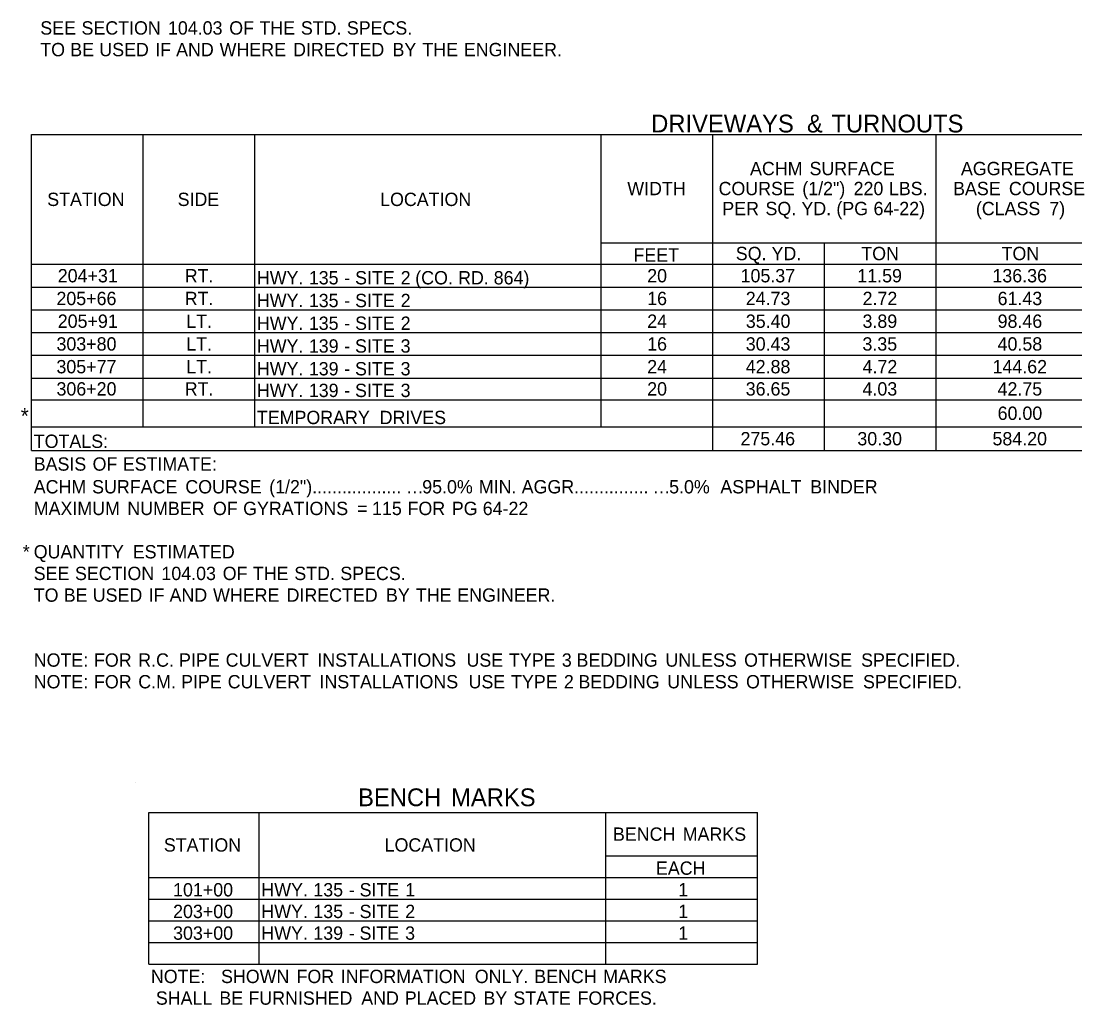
# Model space of a CAD drawing. Extents: x 1955554 to 1962042, y 565952 to 568347.
# Drawn here: x 1956892.3 to 1957366.6, y 566090.6 to 566533.4 of the extents above; entities that cross this region are included whole.
import ezdxf

# ---------------------------------------------------------------- set-up
doc = ezdxf.new("R2010")
doc.units = 0
doc.layers.add('Default', color=7, linetype='Continuous')
doc.layers.add('R_Border', color=7, linetype='Continuous')

msp = doc.modelspace()

# ---------------------------------------------------------------- linework, layer by layer
at = {"layer": 'Default'}
for p, q in [((1956897.02, 566482.45), (1957597.55, 566482.45)), ((1956897.02, 566340.1), (1956897.02, 566482.45)), ((1956897.02, 566340.1), (1956897.02, 566482.45)), ((1956947.23, 566350.82), (1956947.23, 566482.45)), ((1956997.44, 566350.82), (1956997.44, 566482.45)), ((1957153.44, 566350.82), (1957153.44, 566482.45)), ((1957203.65, 566340.1), (1957203.65, 566482.45)), ((1957304.08, 566340.1), (1957304.08, 566482.45)), ((1957153.44, 566433.7), (1957448.87, 566433.7)), ((1957203.65, 566423.95), (1957203.65, 566433.7)), ((1957253.87, 566340.1), (1957253.87, 566433.7)), ((1957304.08, 566340.1), (1957304.08, 566433.7)), ((1956897.02, 566423.95), (1957597.55, 566423.95)), ((1956947.23, 566350.82), (1956947.23, 566423.95)), ((1956997.44, 566350.82), (1956997.44, 566423.95)), ((1957153.44, 566350.82), (1957153.44, 566423.95)), ((1956897.02, 566413.71), (1957597.55, 566413.71)), ((1956897.02, 566403.47), (1957597.55, 566403.47)), ((1956897.02, 566393.24), (1957597.55, 566393.24)), ((1956897.02, 566383), (1957597.55, 566383)), ((1956897.02, 566372.76), (1957597.55, 566372.76)), ((1956897.02, 566363.01), (1957597.55, 566363.01)), ((1956897.02, 566350.82), (1957597.55, 566350.82)), ((1957203.65, 566350.82), (1957253.87, 566350.82)), ((1957203.65, 566340.1), (1957203.65, 566350.82)), ((1957253.87, 566350.82), (1957380.13, 566350.82)), ((1956897.02, 566340.1), (1957597.55, 566340.1)), ((1956949.74, 566177.21), (1957223.72, 566177.21)), ((1956949.74, 566108.96), (1956949.74, 566177.21)), ((1956949.74, 566108.96), (1956949.74, 566177.21)), ((1956999.47, 566108.96), (1956999.47, 566177.21)), ((1957155.47, 566108.96), (1957155.47, 566177.21)), ((1957223.72, 566108.96), (1957223.72, 566177.21)), ((1957155.47, 566157.71), (1957223.72, 566157.71)), ((1957223.72, 566108.96), (1957223.72, 566157.71)), ((1956949.74, 566147.96), (1957223.72, 566147.96)), ((1957155.47, 566108.96), (1957155.47, 566147.96)), ((1956949.74, 566138.21), (1957223.72, 566138.21)), ((1956949.74, 566128.46), (1957223.72, 566128.46)), ((1956949.74, 566118.71), (1957223.72, 566118.71)), ((1956949.74, 566108.96), (1957223.72, 566108.96))]:
    msp.add_line(p, q, dxfattribs=at)
at = {"layer": 'R_Border'}
msp.add_line((1956943.89, 566190.86), (1956943.89, 566190.86), dxfattribs=at)

# ---------------------------------------------------------------- texts
at = {"layer": 'Default'}
for s, height, p in [('SEE', 6, (1956900.93, 566527.36)), (' SECTION', 6, (1956917.26, 566527.36)), (' 104.03', 6, (1956956.17, 566527.36)), (' OF', 6, (1956983.75, 566527.36)), (' THE', 6, (1956997.34, 566527.36)), (' STD.', 6, (1957015.99, 566527.36)), (' SPECS.', 6, (1957036.68, 566527.36)), ('TO', 6, (1956900.93, 566517.61)), (' BE', 6, (1956912.2, 566517.61)), (' USED', 6, (1956925.27, 566517.61)), (' IF', 6, (1956950.44, 566517.61)), (' AND', 6, (1956959.84, 566517.61)), (' WHERE', 6, (1956979.42, 566517.61)), (' DIRECTED', 6, (1957012.5, 566517.61)), (' BY', 6, (1957057.24, 566517.61)), (' THE', 6, (1957070.69, 566517.61)), (' ENGINEER.', 6, (1957089.34, 566517.61)), ('DRIVEWAYS', 8, (1957175.88, 566483.32)), (' &', 8, (1957243.03, 566483.32)), (' TURNOUTS', 8, (1957254.03, 566483.32)), ('ACHM', 6, (1957220.37, 566464.07)), (' SURFACE', 6, (1957244.92, 566464.07)), ('AGGREGATE', 6, (1957315.29, 566464.07)), ('WIDTH', 6, (1957165.13, 566455.07)), ('COURSE', 6, (1957206.22, 566455.07)), (' (1/2")', 6, (1957241.67, 566455.07)), (' 220', 6, (1957264.77, 566455.07)), (' LBS.', 6, (1957280.66, 566455.07)), ('BASE', 6, (1957311.77, 566455.07)), (' COURSE', 6, (1957334.65, 566455.07)), ('STATION', 6, (1956904.06, 566450.2)), ('SIDE', 6, (1956962.76, 566450.2)), ('LOCATION', 6, (1957053.89, 566450.2)), ('PER', 6, (1957207.89, 566446.07)), (' SQ.', 6, (1957225.09, 566446.07)), (' YD.', 6, (1957241.28, 566446.07)), (' (PG', 6, (1957257.01, 566446.07)), (' 64-22)', 6, (1957273.73, 566446.07)), ('(CLASS', 6, (1957322.03, 566446.07)), (' 7)', 6, (1957352.83, 566446.07)), ('FEET', 6, (1957167.92, 566425.15)), ('SQ.', 6, (1957213.96, 566425.82)), (' YD.', 6, (1957227.83, 566425.82)), ('TON', 6, (1957270.46, 566425.82)), ('TON', 6, (1957333.59, 566425.82)), ('204+31', 6, (1956908.8, 566415.83)), ('RT.', 6, (1956965.95, 566415.83)), ('20', 6, (1957174.09, 566415.83)), ('105.37', 6, (1957216.13, 566415.83)), ('11.59', 6, (1957268.67, 566415.83)), ('136.36', 6, (1957329.48, 566415.83)), ('HWY.', 6, (1956998.42, 566414.91)), (' 135', 6, (1957019.57, 566414.91)), (' -', 6, (1957035.54, 566414.91)), (' SITE', 6, (1957040.4, 566414.91)), (' 2', 6, (1957060.92, 566414.91)), (' (CO.', 6, (1957067.46, 566414.91)), (' RD.', 6, (1957086.75, 566414.91)), (' 864)', 6, (1957102.78, 566414.91)), ('205+66', 6, (1956908.21, 566405.59)), ('RT.', 6, (1956965.95, 566405.59)), ('HWY.', 6, (1956998.42, 566404.67)), (' 135', 6, (1957019.57, 566404.67)), (' -', 6, (1957035.54, 566404.67)), (' SITE', 6, (1957040.4, 566404.67)), (' 2', 6, (1957060.92, 566404.67)), ('16', 6, (1957174.08, 566405.59)), ('24.73', 6, (1957218.46, 566405.59)), ('2.72', 6, (1957271.04, 566405.59)), ('61.43', 6, (1957331.81, 566405.59)), ('205+91', 6, (1956908.8, 566395.36)), ('LT.', 6, (1956966.64, 566395.36)), ('HWY.', 6, (1956998.42, 566394.44)), (' 135', 6, (1957019.57, 566394.44)), (' SITE', 6, (1957040.4, 566394.44)), (' 2', 6, (1957060.92, 566394.44)), ('24', 6, (1957174.09, 566395.36)), ('35.40', 6, (1957218.48, 566395.36)), ('3.89', 6, (1957271, 566395.36)), ('98.46', 6, (1957331.81, 566395.36)), (' -', 6, (1957035.54, 566394.44)), ('303+80', 6, (1956908.23, 566385.12)), ('LT.', 6, (1956966.64, 566385.12)), ('HWY.', 6, (1956998.42, 566384.2)), (' 139', 6, (1957019.57, 566384.2)), (' SITE', 6, (1957040.36, 566384.2)), (' 3', 6, (1957060.88, 566384.2)), ('16', 6, (1957174.08, 566385.12)), ('30.43', 6, (1957218.46, 566385.12)), ('3.35', 6, (1957270.98, 566385.12)), ('40.58', 6, (1957331.8, 566385.12)), (' -', 6, (1957035.51, 566384.2)), ('305+77', 6, (1956908.21, 566374.88)), ('LT.', 6, (1956966.64, 566374.88)), ('HWY.', 6, (1956998.42, 566373.96)), (' 139', 6, (1957019.57, 566373.96)), (' SITE', 6, (1957040.36, 566373.96)), (' 3', 6, (1957060.88, 566373.96)), ('24', 6, (1957174.09, 566374.88)), ('42.88', 6, (1957218.46, 566374.88)), ('4.72', 6, (1957271.04, 566374.88)), ('144.62', 6, (1957329.51, 566374.88)), (' -', 6, (1957035.51, 566373.96)), ('306+20', 6, (1956908.23, 566364.89)), ('RT.', 6, (1956965.95, 566364.89)), ('HWY.', 6, (1956998.42, 566364.21)), (' 139', 6, (1957019.57, 566364.21)), (' SITE', 6, (1957040.36, 566364.21)), (' 3', 6, (1957060.88, 566364.21)), ('20', 6, (1957174.09, 566364.89)), ('36.65', 6, (1957218.44, 566364.89)), ('4.03', 6, (1957271.01, 566364.89)), ('42.75', 6, (1957331.79, 566364.89)), (' -', 6, (1957035.51, 566364.21)), ('60.00', 6, (1957331.82, 566353.92)), ('*', 7, (1956892.14, 566352.22)), ('TEMPORARY', 6, (1956998.42, 566352.02)), (' DRIVES', 6, (1957051.46, 566352.02)), ('TOTALS:', 6, (1956897.99, 566341.3)), ('275.46', 6, (1957216.09, 566342.46)), ('30.30', 6, (1957268.69, 566342.46)), ('584.20', 6, (1957329.49, 566342.46)), ('BASIS', 6, (1956897.99, 566331.06)), (' OF', 6, (1956922.25, 566331.06)), (' ESTIMATE:', 6, (1956935.84, 566331.06)), ('ACHM', 6, (1956897.99, 566320.82)), (' SURFACE', 6, (1956922.04, 566320.82)), (' COURSE', 6, (1956963.99, 566320.82)), (' (1/2")..................', 6, (1957001.74, 566320.82)), ('95.0%', 6, (1957072.84, 566320.82)), (' MIN.', 6, (1957096.08, 566320.82)), (' AGGR...............', 6, (1957115.37, 566320.82)), ('5.0%', 6, (1957183.97, 566320.82)), ('  ASPHALT', 6, (1957202.55, 566320.82)), (' BINDER', 6, (1957245.25, 566320.82)), ('MAXIMUM', 6, (1956897.99, 566311.07)), (' NUMBER', 6, (1956937.88, 566311.07)), (' OF', 6, (1956976.42, 566311.07)), (' GYRATIONS', 6, (1956990.01, 566311.07)), (' 115', 6, (1957048.04, 566311.07)), ('…', 6, (1957065.44, 566320.82)), (' FOR', 6, (1957064.01, 566311.07)), (' PG', 6, (1957083.92, 566311.07)), (' 64-22', 6, (1957097.84, 566311.07)), ('…', 6, (1957176.57, 566320.82)), (' =', 6, (1957041.28, 566311.07)), ('*', 6, (1956893.07, 566291.57)), ('QUANTITY', 6, (1956897.99, 566291.57)), (' ESTIMATED', 6, (1956940.31, 566291.57)), ('SEE', 6, (1956897.99, 566281.82)), (' SECTION', 6, (1956914.32, 566281.82)), (' 104.03', 6, (1956953.23, 566281.82)), (' OF', 6, (1956980.81, 566281.82)), (' THE', 6, (1956994.39, 566281.82)), (' STD.', 6, (1957013.04, 566281.82)), (' SPECS.', 6, (1957033.74, 566281.82)), ('TO', 6, (1956897.99, 566272.07)), (' BE', 6, (1956909.26, 566272.07)), (' USED', 6, (1956922.32, 566272.07)), (' IF', 6, (1956947.5, 566272.07)), (' AND', 6, (1956956.89, 566272.07)), (' WHERE', 6, (1956976.47, 566272.07)), (' DIRECTED', 6, (1957009.56, 566272.07)), (' BY', 6, (1957054.3, 566272.07)), (' THE', 6, (1957067.75, 566272.07)), (' ENGINEER.', 6, (1957086.4, 566272.07)), ('NOTE:', 6, (1956897.99, 566242.82)), (' FOR', 6, (1956922.88, 566242.82)), (' R.C.', 6, (1956942.79, 566242.82)), (' PIPE', 6, (1956961.15, 566242.82)), (' CULVERT', 6, (1956982.14, 566242.82)), (' INSTALLATIONS', 6, (1957023.43, 566242.82)), (' USE', 6, (1957090.54, 566242.82)), (' TYPE', 6, (1957109.66, 566242.82)), (' 3', 6, (1957133.44, 566242.82)), (' BEDDING', 6, (1957140.05, 566242.82)), (' UNLESS', 6, (1957180.05, 566242.82)), (' OTHERWISE', 6, (1957215.49, 566242.82)), (' SPECIFIED.', 6, (1957268.14, 566242.82)), ('NOTE:', 6, (1956897.99, 566233.07)), (' FOR', 6, (1956922.88, 566233.07)), (' C.M.', 6, (1956942.79, 566233.07)), (' PIPE', 6, (1956962.08, 566233.07)), (' CULVERT', 6, (1956983.06, 566233.07)), (' INSTALLATIONS', 6, (1957024.36, 566233.07)), (' USE', 6, (1957091.47, 566233.07)), (' TYPE', 6, (1957110.59, 566233.07)), (' 2', 6, (1957134.37, 566233.07)), (' BEDDING', 6, (1957140.91, 566233.07)), (' UNLESS', 6, (1957180.91, 566233.07)), (' OTHERWISE', 6, (1957216.35, 566233.07)), (' SPECIFIED.', 6, (1957269, 566233.07)), ('BENCH', 8, (1957043.96, 566180.04)), (' MARKS', 8, (1957082.85, 566180.04)), ('BENCH', 6, (1957158.68, 566164.46)), (' MARKS', 6, (1957187.85, 566164.46)), ('STATION', 6, (1956956.55, 566159.59)), ('LOCATION', 6, (1957055.92, 566159.59)), ('EACH', 6, (1957178.04, 566149.16)), ('101+00', 6, (1956960.71, 566139.41)), ('HWY.', 6, (1957000.44, 566139.41)), (' 135', 6, (1957021.6, 566139.41)), (' -', 6, (1957037.57, 566139.41)), (' SITE', 6, (1957042.43, 566139.41)), (' 1', 6, (1957062.95, 566139.41)), ('1', 6, (1957188.03, 566139.41)), ('203+00', 6, (1956960.71, 566129.66)), ('HWY.', 6, (1957000.44, 566129.66)), (' 135', 6, (1957021.6, 566129.66)), (' -', 6, (1957037.57, 566129.66)), (' SITE', 6, (1957042.43, 566129.66)), (' 2', 6, (1957062.95, 566129.66)), ('1', 6, (1957188.03, 566129.66)), ('303+00', 6, (1956960.71, 566119.91)), ('HWY.', 6, (1957000.44, 566119.91)), (' 139', 6, (1957021.6, 566119.91)), (' -', 6, (1957037.54, 566119.91)), (' SITE', 6, (1957042.39, 566119.91)), (' 3', 6, (1957062.91, 566119.91)), ('1', 6, (1957188.03, 566119.91)), ('NOTE:', 6, (1956950.72, 566100.41)), ('   SHOWN', 6, (1956975.61, 566100.41)), (' FOR', 6, (1957014.04, 566100.41)), (' INFORMATION', 6, (1957033.95, 566100.41)), (' ONLY.', 6, (1957094.28, 566100.41)), (' BENCH', 6, (1957121.03, 566100.41)), (' MARKS', 6, (1957152.03, 566100.41)), (' SHALL', 6, (1956950.72, 566090.66)), (' BE', 6, (1956979.31, 566090.66)), (' FURNISHED', 6, (1956992.38, 566090.66)), (' AND', 6, (1957043.17, 566090.66)), (' PLACED', 6, (1957062.75, 566090.66)), (' BY', 6, (1957098.18, 566090.66)), (' STATE', 6, (1957111.63, 566090.66)), (' FORCES.', 6, (1957140.53, 566090.66))]:
    msp.add_text(s, height=height, dxfattribs=at).set_placement(p)

doc.saveas('drawing.dxf')
